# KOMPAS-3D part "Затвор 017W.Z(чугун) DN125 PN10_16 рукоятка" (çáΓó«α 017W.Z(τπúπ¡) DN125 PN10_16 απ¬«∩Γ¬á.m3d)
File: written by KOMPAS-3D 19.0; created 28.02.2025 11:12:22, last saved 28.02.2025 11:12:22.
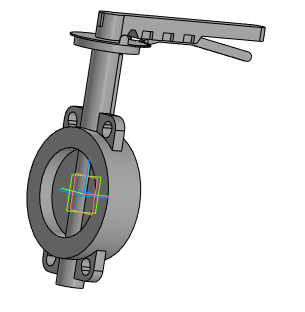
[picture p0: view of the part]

Document properties: Автор: Евгений; Полное имя файла: Затвор 017W.Z(чугун) DN125 PN10_16 рукоятка.a3d

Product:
- Part/product: Затвор 017W.Z(чугун) DN125 PN10_16 рукоятка
    Масса: 18.443

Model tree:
1. Операция без истории:1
